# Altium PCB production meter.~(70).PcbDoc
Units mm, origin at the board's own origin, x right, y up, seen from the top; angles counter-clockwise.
Board outline 120 x 34 mm, 2 copper layers (Top Layer, Bottom Layer); 57 components, 53 nets, 214 pads, 22 vias.
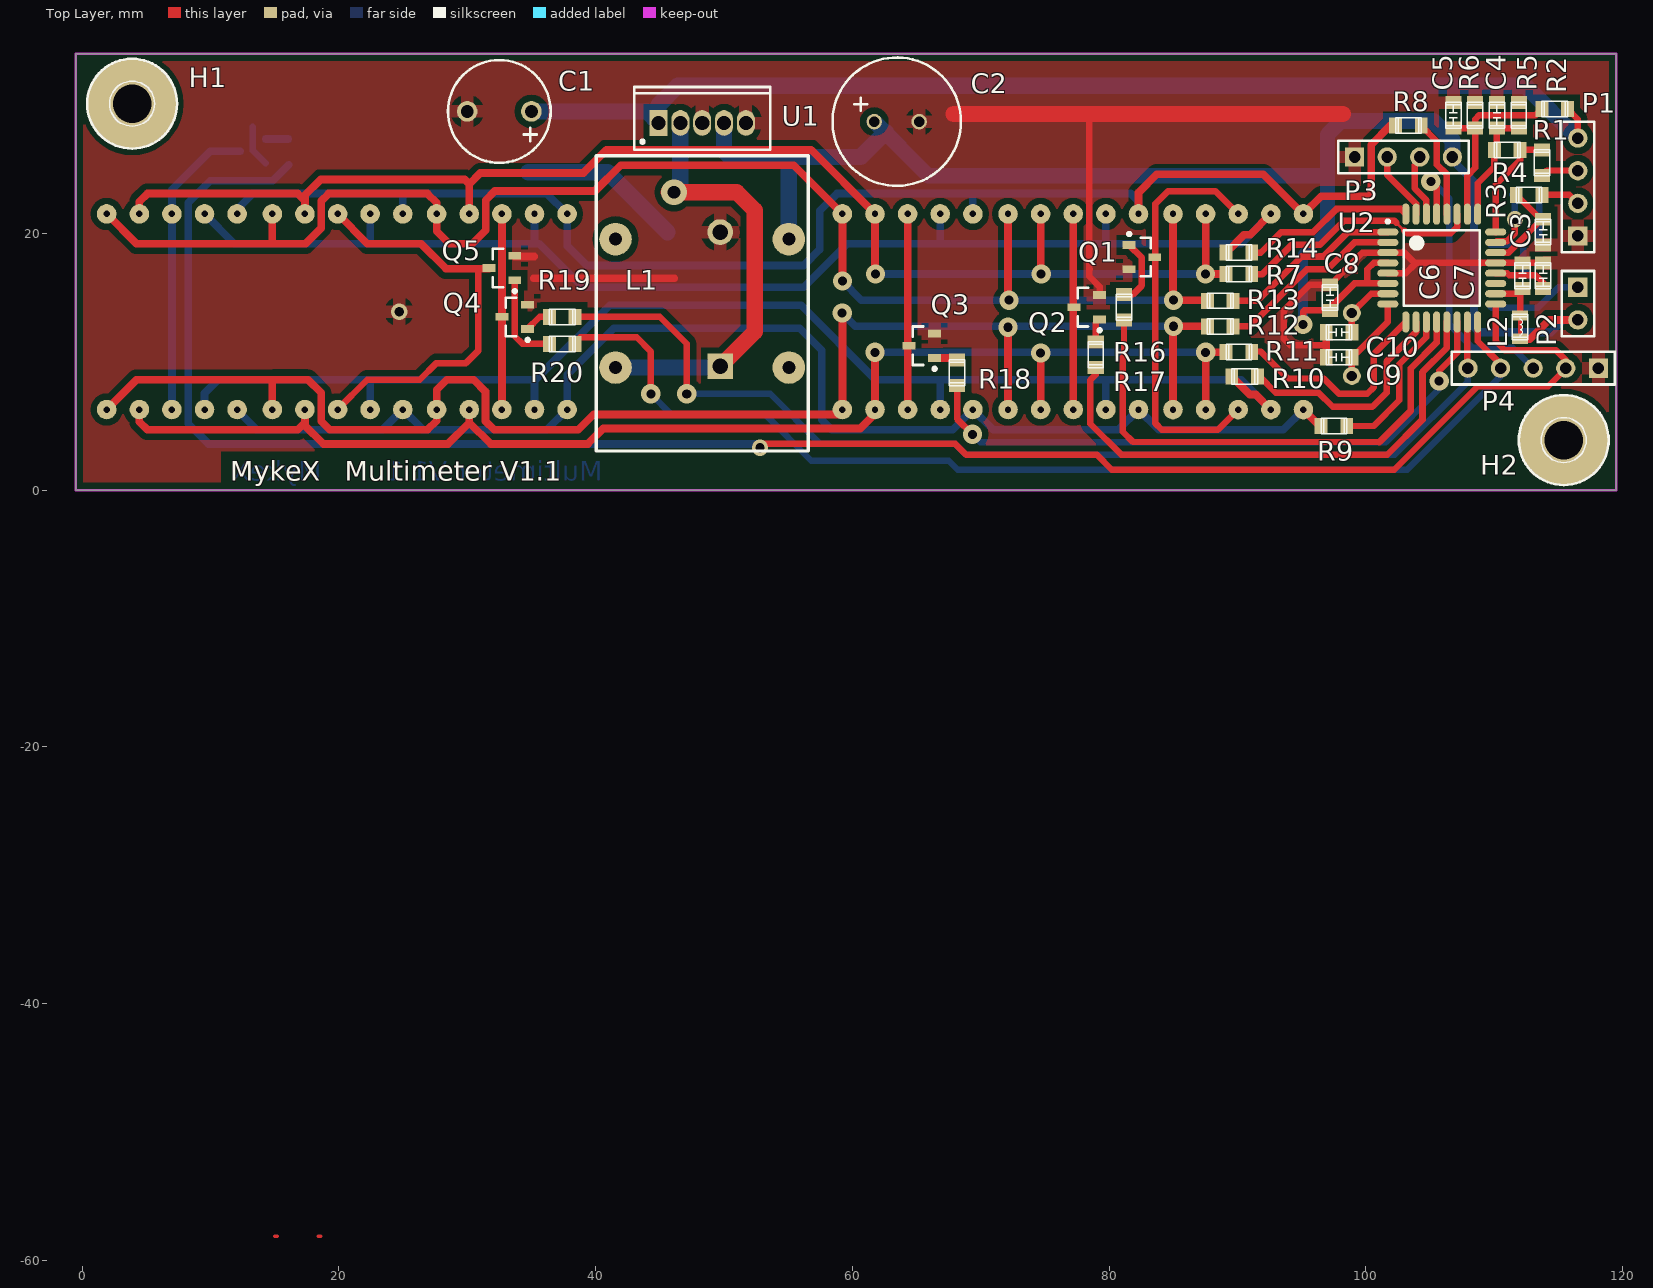
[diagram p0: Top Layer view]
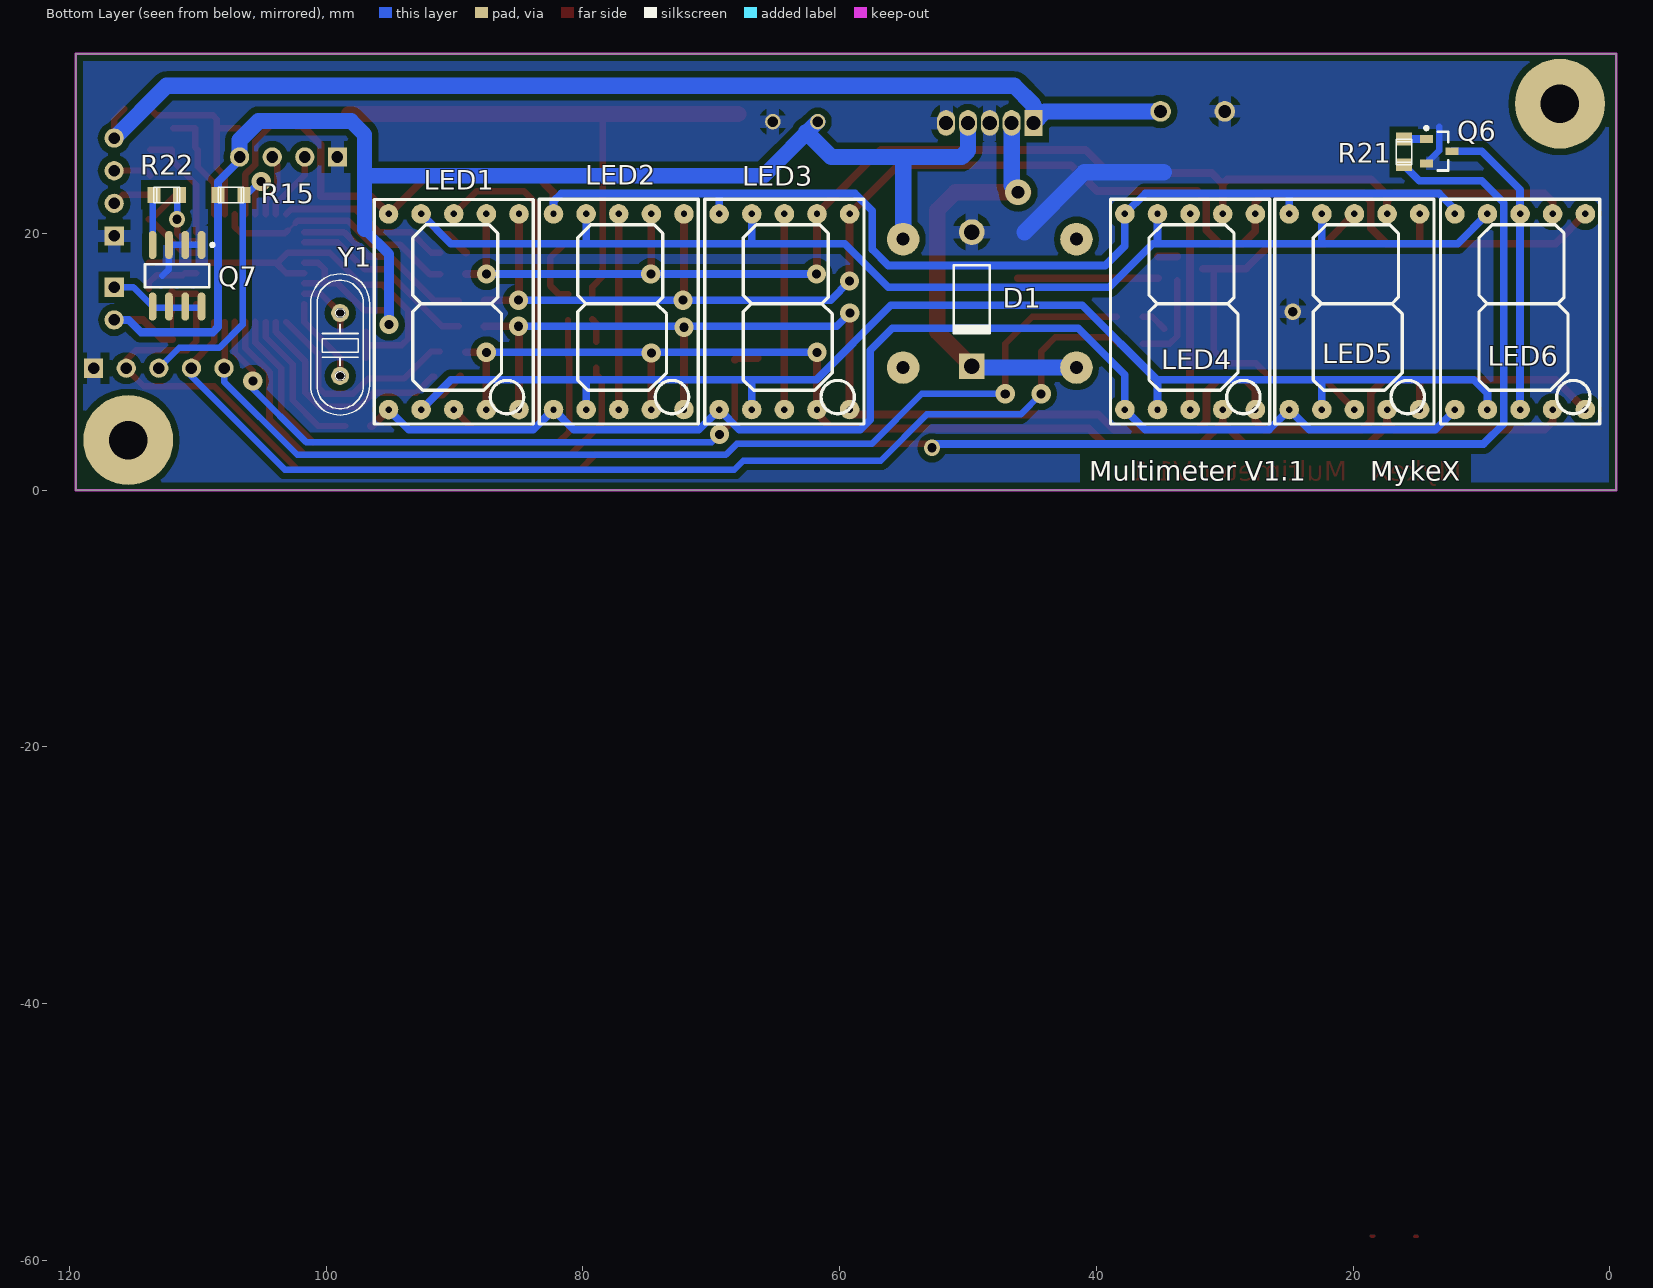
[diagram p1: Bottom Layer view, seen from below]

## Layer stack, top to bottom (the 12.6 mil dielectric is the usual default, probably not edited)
Top Layer: signal copper 0.0356
Dielectric: dielectric 0.32, FR-4, Dk 4.8
Bottom Layer: signal copper 0.0356

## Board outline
-0.5,0 -0.5,34 119.5,34 119.5,0

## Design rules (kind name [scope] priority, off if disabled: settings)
Clearance PolygonGND [InPolygon] p1: gap=0.5
Clearance [All] p2: gap=0.2
ComponentClearance [All] p1: gap=0.1 collisioncheckmode=3 verticalgap=0 showdistances=FALSE
HoleSize [All] p1: absolutevalues=TRUE maxlimit=5 minlimit=0.025 maxpercent=80.000 minpercent=20.000
MinimumSolderMaskSliver [All] p1: minsoldermaskwidth=0
PlaneClearance [All] p1: clearance=1
PlaneClearance PlaneClearance_1 [All] p2: clearance=0.8
PolygonConnect [All] p1: connectstyle=Relief reliefconductorwidth=1 reliefentries=4 polygonreliefangle="90 Angle"
RoomDefinition "production meter" [InComponentClass('production meter')] p1: confinementstyle=ConfineIn formatcopy=TRUE lockcomponents=FALSE outline -38,-58.1 12.8,-58.1 12.8,-32.7 -38,-32.7
RoutingVias [All] p1: holewidth=0.711 width=1.27 viastyle="Through Hole" minholewidth=0.711 minwidth=1.27 maxholewidth=2 maxwidth=2
SilkToSilkClearance [All] p1: silktosilkclearance=0
SilkscreenOverComponentPads [All] p1: minsilkscreentomaskgap=0
SolderMaskExpansion SolderMaskOverVia [(IsVia)] p1: expansion=-10
SolderMaskExpansion [All] p2: expansion=0.102
Width [All] p1: maxlimit=2 minlimit=0.2 preferedwidth=0.5
22 further rules are at their usual default settings.

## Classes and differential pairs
net class PD[7..0]: PD0 PD1 PD2 PD3 PD4 PD5 PD6 PD7
net class PB[5..0]: PB0 PB1 PB2 PB3 PB4 PB5

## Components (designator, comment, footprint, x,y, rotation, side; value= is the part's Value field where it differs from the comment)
C1 "100uFx50V" CEd8p5 35,29.5 r180 top
C2 "1000uFx3.6V" CEd10p3.5 61.7,28.7 r0 top
C3 "0.1uF" C0805\2P 113.8,21 r270 top
C4 "0.1uF" C0805\2P 110.2,28.3 r90 top
C5 "0.1uF" C0805\2P 106.8,28.3 r90 top
C6 "0.1uF" C0805\2P 112.2,17.6 r270 top
C7 "0.1uF" C0805\2P 113.8,17.6 r270 top
C8 "0.1uF" C0805\2P 97.2,14.1 r90 top
C9 "22pF" C0805\2P 97,10.352 r0 top
C10 "22pF" C0805\2P 97,12.3 r0 top
D1 "Diode 11DQ03" DIO10.46-5.3x2.8 49.7,14.87 r270 bottom
H1 "Hole_3mm" F3.5X7.5_Met_NH 3.9,30.1 r0 top
H2 "Hole_3mm" F3.5X7.5_Met_NH 115.4,3.9 r0 top
L1 "Inductor 330uH 1A" "Inductor footprint" 55.05,3.3 r90 top
L2 "47uH" LL0805\2P 112,13.6 r270 top
LED1 "SA52-11GWA" SA52-11GWA 96.249,5.148 r180 bottom
LED2 "SA52-11GWA" SA52-11GWA 83.4,5.15 r180 bottom
LED3 "SA52-11GWA" SA52-11GWA 70.5,5.15 r180 bottom
LED4 "SA52-11GWA" SA52-11GWA 38.9,5.15 r180 bottom
LED5 "SA52-11GWA" SA52-11GWA 26.1,5.15 r180 bottom
LED6 "SA52-11GWA" SA52-11GWA 13.2,5.15 r180 bottom
P1 "Header 4" HDR1X4 116.5,19.8 r90 top
P2 "Fan" HDR1X2 116.5,15.8 r270 top
P3 "UART" HDR1X4 99.11,25.95 r0 top
P4 "ISP Header" HDR1X5 118.1,9.5 r180 top
Q1 "BC847C" SOT23_L 82.55,18.15 r0 top
Q2 "BC847C" SOT23_L 78.25,14.25 r180 top
Q3 "BC847C" SOT23_L 65.4,11.25 r180 top
Q4 "BC847C" SOT23_L 33.7,13.5 r180 top
Q5 "BC847C" SOT23_L 32.7,17.3 r180 top
Q6 "BC847C" SOT23_L 13.3,26.4 r180 bottom
Q7 "IRF7811AV" SO-8_N 111.6,16.7 r270 bottom
R1 "260k" R0805\2P 113.7,26.4 r270 top
R2 "260k" R0805\2P 113.8,29.7 r0 top
R3 "1k" R0805\2P 111.8,23 r0 top
R4 "15k" R0805\2P 110.1,26.5 r0 top
R5 "30k" R0805\2P 111.9,30.1 r270 top
R6 "15k" R0805\2P 108.5,30.1 r270 top
R7 "180" R0805\2P 91,16.832 r180 top
R8 "180" R0805\2P 104.2,28.4 r180 top
R9 "180" R0805\2P 98.4,5 r180 top
R10 "180" R0805\2P 91.45,8.85 r180 top
R11 "180" R0805\2P 91,10.75 r180 top
R12 "180" R0805\2P 89.55,12.75 r180 top
R13 "180" R0805\2P 89.55,14.75 r180 top
R14 "180" R0805\2P 91,18.5 r180 top
R15 "10k" R0805\2P 108.3,23 r180 bottom
R16 "1k" R0805\2P 81.15,13.35 r90 top
R17 "1k" R0805\2P 78.95,9.65 r90 top
R18 "1k" R0805\2P 68.15,8.25 r90 top
R19 "1k" R0805\2P 38.3,13.5 r180 top
R20 "1k" R0805\2P 38.3,11.4 r180 top
R21 "1k" R0805\2P 16.05,25.45 r90 bottom
R22 "1k" R0805\2P 111.5,23 r0 bottom
U1 "LM2575T-5.0" T05A 48.3,28.6 r0 top
U2 "ATmega8-16AI" 32A_N 105.9,17.3 r0 top
Y1 "XTAL" XTAL_AXIAL_L11W4.6P4.9 98.9,13.8 r270 bottom

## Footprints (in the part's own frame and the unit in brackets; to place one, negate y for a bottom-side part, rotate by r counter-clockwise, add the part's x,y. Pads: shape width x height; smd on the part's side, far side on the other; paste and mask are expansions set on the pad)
32A_N [mm] "Thin QFP, 32-Leads, Body 7x7mm, Pitch 0.8mm, IPC Medium Density"
  oval 1.65x0.55 smd: 1(-4.2,2.8) 2(-4.2,2) 3(-4.2,1.2) 4(-4.2,0.4) 5(-4.2,-0.4) 6(-4.2,-1.2) 7(-4.2,-2) 8(-4.2,-2.8) 17(4.2,-2.8) 18(4.2,-2) 19(4.2,-1.2) 20(4.2,-0.4) 21(4.2,0.4) 22(4.2,1.2) 23(4.2,2) 24(4.2,2.8)
  oval 0.55x1.65 smd: 9(-2.8,-4.2) 10(-2,-4.2) 11(-1.2,-4.2) 12(-0.4,-4.2) 13(0.4,-4.2) 14(1.2,-4.2) 15(2,-4.2) 16(2.8,-4.2) 25(2.8,4.2) 26(2,4.2) 27(1.2,4.2) 28(0.4,4.2) 29(-0.4,4.2) 30(-1.2,4.2) 31(-2,4.2) 32(-2.8,4.2)
  silkscreen extent -4.32,-2.95 2.95,3.75, body extent -3.5,-3.5 3.5,3.5, height 1.2
C0805\2P [mm]
  rect 1x1.25 smd: 1(-0.1,0) 2(1.9,0)
  silkscreen extent -0.1,-0.6 1.9,0.6
CEd8p5 [mm] "Electrolytic capacitor, Diameter 8mm, Pitch 5mm"
  round 1.6 hole 1: 1(0,0) 2(5,0)
  silkscreen extent -1.5,-4 6.5,4
CEd10p3.5 [mm] "Electrolytic capacitor, Diameter 10mm, Pitch 3.5mm"
  round 1.2 hole 0.8: 1(0,0) 2(3.5,0)
  silkscreen extent -3.25,-5 6.75,5
DIO10.46-5.3x2.8 [mm] "Diode, Axial; Body 5.2 x 2.7 mm (LxDia. max), Lead Dia. 0.86 mm (max)"
  round 2 hole 1.2: 1(-5.23,0)
  rect 2x2 hole 1.2: 2(5.23,0)
  silkscreen extent -2.65,-1.41 2.75,1.4
F3.5X7.5_Met_NH [mm]
  round 7 hole 3: 0(0,0)
  silkscreen extent -3.5,-3.5 3.5,3.5
HDR1X2 [mm] "Connector; Header; 2 Position"
  rect 1.5x1.5 hole 0.9: 1(0,0)
  round 1.5 hole 0.9: 2(2.54,0)
  silkscreen extent -1.27,-1.27 3.81,1.27
HDR1X4 [mm] "Connector; Header; 4 Position"
  rect 1.5x1.5 hole 0.9: 1(0,0)
  round 1.5 hole 0.9: 2(2.54,0) 3(5.08,0) 4(7.62,0)
  silkscreen extent -1.27,-1.27 8.89,1.27
HDR1X5 [mm] "Connector; Header; 5 Position"
  rect 1.5x1.5 hole 0.9: 1(0,0)
  round 1.5 hole 0.9: 2(2.54,0) 3(5.08,0) 4(7.62,0) 5(10.16,0)
  silkscreen extent -1.27,-1.27 11.43,1.27
"Inductor footprint" [mm]
  round 2.54 hole 1: 0(6.25,0) 0(16.25,13.5) 1(6.25,13.5) 2(16.25,0)
  silkscreen extent -0.25,-1.5 22.75,15
LL0805\2P [mm]
  rect 0.8x1.25 smd: 1(0,0) 2(1.8,0)
  silkscreen extent -0.1,-0.6 1.9,0.6
R0805\2P [mm]
  rect 1x1.25 smd: 1(-0.1,0) 2(1.9,0)
  silkscreen extent -0.1,-0.6 1.9,0.6
SA52-11GWA [mm]
  round 1.524 hole 0.5: 1(1.12,1.13) 2(3.66,1.13) 3(6.2,1.13) 4(8.74,1.13) 5(11.28,1.13) 6(11.28,16.37) 7(8.74,16.37) 8(6.2,16.37) 9(3.66,16.37) 10(1.12,16.37)
  silkscreen extent 0,0 12.4,17.5
SO-8_N [mm] "SOIC, 8-Leads, Body 4.9x3.9mm, Pitch 1.27mm, IPC Medium Density"
  oval 2.2x0.6 smd: 1(-2.4,1.905) 2(-2.4,0.635) 3(-2.4,-0.635) 4(-2.4,-1.905) 5(2.4,-1.905) 6(2.4,-0.635) 7(2.4,0.635) 8(2.4,1.905)
  silkscreen extent -2.52,-2.5 0.9,2.88, body extent -1.95,-2.45 1.95,2.45, height 1.75
SOT23_L [mm] "SOT23, 3-Leads, Body 2.9x1.3mm, Pitch 0.95mm, Lead Span 2.3mm, IPC High Density"
  rect 1x0.6 smd: 1(-1,0.95) 2(-1,-0.95) 3(1,0)
  silkscreen extent -1.12,-1.5 0.7,1.92, body extent -0.7,-1.5 0.7,1.5, height 1.1
T05A [mm] "TO, Thru-Hole, Vertical, Heatsink Mounted; 5 In-Line Leads; Pitch 1.70 mm"
  rect 1.4x2 hole 1.1: 1(-3.4,0)
  oval 1.4x2 hole 1.1: 2(-1.7,0) 3(0,0) 4(1.7,0) 5(3.4,0)
  silkscreen extent -5.3,-2.1 5.3,2.8
XTAL_AXIAL_L11W4.6P4.9 [mm] "Quartz Crystal"
  round 1.4 hole 0.8: 1(0,0) 2(4.9,0)
  silkscreen extent -3.05,-2.3 7.95,2.3

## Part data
C1 C2: library part Cap_Elect, "Electrolytic capacitor"
C3 C4 C5 C6 C7 C8 C9 C10: library part Cap_Cer, "Capacitor ceramic"
D1: "Schottky Rectifier"
L1: library part "Inductor 330uH 1A_1"
L2: library part Inductor
P1: "Header, 4-Pin"
P2: library part "Header 2", "Header, 2-Pin"
P3: library part "Header 4", "Header, 4-Pin"
P4: library part "Header 5", "Header, 5-Pin"
Q1 Q2 Q3 Q4 Q5 Q6: "NPN General-purpose Transistor"
Q7: "HEXFET Power MOSFET"
R1 R2 R3 R4 R5 R6 R7 R8 R9 R10 R11 R12 R13 R14 R15 R16 R17 R18 R19 R20 R21 R22: library part Res, "Resistor"
U1: "SIMPLE SWITCHER 1A Step-Down Voltage Regulator"
U2: "8-Bit AVR Microcontroller with 8K Bytes of In-System Programmable Flash Memory"
Y1: "Quartz Crystal"

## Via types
v1: diameter 1.5, hole 0.711, Top Layer to Bottom Layer, 18 vias
v2: diameter 1.27, hole 0.711, Top Layer to Bottom Layer, 3 vias
v3: diameter 2, hole 1, Top Layer to Bottom Layer, 1 vias

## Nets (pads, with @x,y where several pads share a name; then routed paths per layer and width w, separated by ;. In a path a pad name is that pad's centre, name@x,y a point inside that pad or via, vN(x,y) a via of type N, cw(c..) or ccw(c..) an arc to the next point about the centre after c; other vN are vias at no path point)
GND: C1.2 C2.2 C3.2 C4.2 C5.2 C6.1 C7.1 C8.2 C9.1 C10.1 D1.1 P1.1 P3.1 P4.1 Q1.2 Q2.2 Q3.2 Q4.2 Q5.2 Q6.2 Q7.1 Q7.2 Q7.3 R5.1 R6.1 U1.3 U1.5 U2.3 U2.5 U2.21 | length 110.7
  Top Layer w0.5: 78.45,29.3 78.45,17.25 ; 78.5,17.2 78.45,17.25 ; Q2.2 79.25,15.85 78.45,16.65 78.45,17.25 ; 96.9,11.3 94.1,11.3 93.6,11.8 93.6,14 95.6,16 C8.2@97,16 ; C8.2@97.217,16 99.717,18.5 U2.3 103,18.5 103.8,17.7 U2.21 C6.1 C7.1 ; U2.5 103.1,16.9 103.85,17.65
  Top Layer w0.6: Q5.2@33.7,18.2 35.2,18.2 ; 35.2,16.5 46.1,16.5 ; C9.1 96.9,11.3 C10.1
  Top Layer w1.27: 67.9,29.3 78.45,29.3 98.2,29.3
  Bottom Layer w0.5: 13.3,28.3 13.3,26.45 Q6.2 ; Q7.1 Q7.2 Q7.3 112.235,17.215 112.75,16.7
  Bottom Layer w1.27: 34.75,24.75 40.95,24.75 45.6,20.1
  other v2: 24.7,13.9
NetC1_1: C1.1 P1.4 R2.2 U1.1 | length 88.2
  Top Layer w0.5: R2.2 116.5,28.9 P1.4 P1.4@116.48,27.42
  Bottom Layer w1.27: C1.1 44,29.5 U1.1 44.9,30 46.4,31.5 112.42,31.5 P1.4
NetC3_1: C3.1 R3.1 U2.22 | length 7.6
  Top Layer w0.5: U2.22 111.1,18.5 C3.1@113.7,21.1 ; R3.1 113.6,21.1 C3.1@113.7,21.1 ; C3.1 C3.1@113.7,21.1
NetC4_1: C4.1 R4.1 R5.2 U2.25 | length 9
  Top Layer w0.5: U2.25 108.7,23.9 110,25.2 R4.1 110.2,26.7 C4.1 R5.2
NetC5_1: C5.1 R2.1 R6.2 U2.26 | length 14.9
  Top Layer w0.5: C5.1 R6.2 ; U2.26 107.9,24.5 108.5,25.1 R6.2 ; R2.1 113.2,29.2 108.8,29.2 108.5,28.9 R6.2
NetC7_2: C7.2 U2.20 | length 4.5
  Top Layer w0.5: U2.20 111,16.9 111.15,16.75 113.2,16.75 113.8,16.15 C7.2
NetC9_2: C9.2 U2.8 Y1.2 | length 6.8
  Top Layer w0.5: Y1.2 98.9,10.3 101.7,13.1 U2.8
NetC10_2: C10.2 U2.7 Y1.1 | length 4.9
  Top Layer w0.5: C10.2 Y1.1 100.4,15.3 U2.7
NetD1_2: D1.2 L1.1 U1.2 | length 34.3
  Top Layer w1.27: v3@45.7,23.2 51,23.2 52.4,21.8 52.4,12.34 D1.2
  Bottom Layer w1.27: L1.1 D1.2@49.7,9.55 ; v3(46.1,23.2) 46.6,23.7 U1.2
NetLED1_3: LED1.3 LED1.8 Q1.3 | length 32.1
  Top Layer w0.508: LED1.8 88.267,23.3 84.6,23.3 83.6,22.3 83.6,5.2 84.1,4.7 88.471,4.7 LED1.3 LED1.3@90.1,6.227
NetLED2_3: LED2.3 LED2.8 Q2.3 | length 15.2
  Top Layer w0.6: LED2.3 LED2.8
NetLED3_3: LED3.3 LED3.8 Q3.3 | length 15.2
  Top Layer w0.6: LED3.3 LED3.8
NetLED4_3: LED4.3 LED4.8 Q4.3 | length 15.2
  Top Layer w0.6: LED4.3 LED4.8
NetLED5_3: LED5.3 LED5.8 Q5.3 | length 33.6
  Top Layer w0.508: LED5.3 22.22,8.6 26.3,8.6 27.6,9.9 29.9,9.9 30.87,10.87 30.87,17.25 Q5.3@31.7,17.25
  Top Layer w0.6: LED5.8 22.22,19.2 26.4,19.2 28.35,17.25 Q5.3@31.7,17.25
NetLED6_3: LED6.3 LED6.8 Q6.3 | length 23.7
  Bottom Layer w0.6: LED6.3 LED6.8 7,23.4 10,26.4 Q6.3
NetP1_2: P1.2 R3.2 | length 3.1
  Top Layer w0.5: R3.2 115.84,23 P1.2
NetP1_3: P1.3 R1.2 | length 3
  Top Layer w0.5: R1.2 114.1,24.9 116.48,24.9 P1.3
NetP2_1: P2.1 Q7.5 Q7.6 Q7.7 Q7.8 | length 7.7
  Bottom Layer w0.5: Q7.8 109.795,14.2 112.235,14.2 Q7.5@113.4,14.2 ; Q7.5@113.5,14.3 Q7.5@113.4,14.2 ; P2.1 115,15.8 Q7.5@113.4,14.2
NetP3_2: P3.2 U2.31 | length 5.1
  Top Layer w0.5: P3.2@101.64,25.7 101.64,24.56 103.9,22.3 U2.31
NetP3_3: P3.3 U2.30 | length 4.7
  Top Layer w0.5: P3.3@104.18,25.7 103.8,25.32 103.8,23.5 104.7,22.6 U2.30
NetP4_3: P4.3 R15.2 U2.29 | length 22.5
  Top Layer w0.5: v1@105,24.1 105.5,23.6 U2.29
  Bottom Layer w0.5: v1@105.1,24.1 106.5,22.7 106.5,12.9 108.3,11.1 111.42,11.1 P4.3
  other v1: 105.05,24.05
NetQ1_1: Q1.1 R16.2 | length 5.3
  Top Layer w0.508: R16.2 81.85,15.25 82.55,15.95 82.55,18.1 Q1.1
NetQ2_1: Q2.1 R17.2 | length 1.9
  Top Layer w0.508: R17.2 78.95,13 Q2.1
NetQ3_1: Q3.1 R18.2 | length 1.8
  Top Layer w0.6: Q3.1 68,10.3 R18.2
NetQ4_1: Q4.1 R19.2 | length 2.1
  Top Layer w0.5: Q4.1 35.65,13.5 R19.2
NetQ5_1: Q5.1 R20.2 | length 7.3
  Top Layer w0.5: Q5.1 33.7,12 34.3,11.4 R20.2
NetQ6_1: Q6.1 R21.2 | length 1.7
  Bottom Layer w0.6: Q6.1 R21.2
NetQ7_4: Q7.4 R22.2 | length 4
  Bottom Layer w0.5: Q7.4 R22.2@113.505,23.1
NetR1_1: R1.1 R4.2 U2.24 | length 8.9
  Top Layer w0.5: U2.24 110.1,23.8 112,25.7 R4.2 R1.1
NetR7_1: R7.1 U2.27 | length 19.2
  Top Layer w0.2: 102.5,20.7 102.975,20.225
  Top Layer w0.5: 102.975,20.225 103.2,20 106.6,20 107.1,20.5 U2.27
  Top Layer w0.508: R7.1@91.1,16.8 91.9,16.8 94.2,19.1 96.4,19.1 98.3,21 102.2,21 102.371,20.829
NetR8_1: R8.1 U2.28 | length 7.7
  Top Layer w0.508: R8.1 105.516,27.184 105.516,25.364 106.3,24.58 U2.28
NetR9_1: R9.1 U2.11 | length 11.9
  Top Layer w0.5: R9.1 100.6,5 102.6,7 102.6,9.8 104.7,11.9 U2.11
NetR10_1: R10.1 U2.10 | length 17.9
  Top Layer w0.5: R10.1 91.731,8.85 92.981,7.6 96.3,7.6 97.4,6.5 100.5,6.5 101.6,7.6 101.6,10.025 103.9,12.325 U2.10
NetR11_1: R11.1 U2.9 | length 17.2
  Top Layer w0.5: R11.1@91.15,10.8 91.8,10.8 92.15,10.45 93.9,8.7 96.7,8.7 97.9,7.5 100.1,7.5 100.6,8 100.6,10.6 U2.9
NetR12_1: R12.1 U2.2 | length 14.8
  Top Layer w0.508: R12.1 90.95,12.75 95.4,17.2 97,17.2 99.1,19.3 U2.2
NetR13_1: R13.1 U2.1 | length 14.3
  Top Layer w0.508: R13.1 91.55,14.75 95,18.2 96.7,18.2 98.6,20.1 U2.1
NetR14_1: R14.1 U2.32 | length 13.6
  Top Layer w0.508: R14.1 91.8,18.5 93.4,20.1 95.9,20.1 97.7,21.9 102.7,21.9 U2.32
NetR22_1: R22.1 U2.23 | length 4.9
  Top Layer w0.5: U2.23 110.175,19.375 110.95,19.375 111.6,20.025 v2(111.6,21.1)
  Bottom Layer w0.5: R22.1 111.6,22.8 v2(111.6,21.1)
PB0: R16.1 U2.12 | length 40.3
  Top Layer w0.5: R16.1 81.15,10.45 81.05,10.35 81.05,4.55 81.85,3.75 101.05,3.75
  Top Layer w0.508: 101.05,3.75 103.5,6.2 103.5,9.5 105.5,11.5 U2.12
PB1: R17.1 U2.13 | length 41
  Top Layer w0.508: 78.55,8.6 78.524,8.574 ; R17.1 78.95,9 78.524,8.574 ; U2.13 106.3,11.1 104.4,9.2 104.4,5.5 101.65,2.75 80.95,2.75 78.524,5.176 78.524,8.574
PB2: R18.1 U2.14 | length 48.5
  Top Layer w0.508: R18.1@68.15,8.25 68.15,5.55 v1(69.35,4.35) ; v1(105.7,8.5) 105.7,9.3 107.1,10.7 U2.14
  Bottom Layer w0.508: v1(69.35,4.35) 69.95,3.75 101.55,3.75 105.7,7.9 v1(105.7,8.5)
PB3: P4.5 R19.1 U2.15 | length 83.3
  Top Layer w0.5: R19.1 45,13.5 47.1,11.4 v1(47.1,7.5) ; P4.5@107.9,9.5 U2.15
  Bottom Layer w0.5: v1(47.1,7.5) 53.6,7.5 57.5,3.6 68,3.6 68.85,2.75 102.25,2.75 107.94,8.44 P4.5
PB4: P4.4 R20.1 U2.16 | length 87
  Top Layer w0.5: R20.1@38.3,11.4 38.8,11.9 43.2,11.9 44.3,10.8 v1(44.3,7.5) ; U2.16 108.7,11.6 110.48,9.82 P4.4@110.48,9.02
  Bottom Layer w0.5: v1(44.3,7.5) 45.9,5.9 53.2,5.9 56.8,2.3 67.5,2.3 68.2,1.6 103.2,1.6 110.48,8.88 P4.4
PB5: P4.2 R21.1 U2.17 | length 148
  Top Layer w0.5: v2@52.9,3.5 53,3.6 68,3.6 68.85,2.75 79.05,2.75 80.2,1.6 102.2,1.6 108.7,8.1 114.2,8.1 115.56,9.46 115.56,10.14 114.8,10.9 110.8,10.9 110.1,11.6 U2.17
  Bottom Layer w0.6: R21.1@16.1,25.35 14.85,24.1 10,24.1 8.278,22.378 8.278,5.172 9.85,3.6 52.5,3.6 v2(52.8,3.3)
PD0: LED1.10 LED2.10 LED3.10 LED4.10 LED5.10 LED6.10 R8.2 | length 112
  Top Layer w0.6: LED2.10 82.28,23.18 83.7,24.6 92,24.6 95.082,21.518 LED1.10 96.511,22.9 100.4,22.9 100.4,26.9 101.9,28.4 R8.2
  Bottom Layer w0.6: LED6.10 12.08,21.88 13.3,23.1 25,23.1 ; LED5.10 24.98,23.08 25,23.1 ; LED3.10 69.38,23.08 ; LED2.10 82.28,22.5 81.68,23.1 58.8,23.1 57.45,21.75 57.45,18.75 56.2,17.5 39.3,17.5 37.78,19.02 LED4.10 36.2,23.1 25,23.1
PD1: LED1.9 LED2.9 LED3.9 LED4.9 LED5.9 LED6.9 R14.2 | length 101.6
  Top Layer w0.6: R14.2 90.5,19.9 90.971,19.9 LED1.9
  Bottom Layer w0.6: LED6.9 11.86,19.2 35.6,19.2 39,15.8 56.2,15.8 59.6,19.2 90.271,19.2 LED1.9 ; 22.44,19.24 LED5.9 ; 35.24,19.24 LED4.9 ; 66.84,19.24 LED3.9 ; 79.74,19.24 LED2.9
PD2: LED1.7 LED2.7 LED3.7 LED4.7 LED5.7 LED6.7 R7.2 | length 107.6
  Top Layer w0.6: LED6.7 4.46,22.46 5.1,23.1 16.8,23.1 17.36,22.54 ; LED5.7 17.36,22.54 ; LED4.7 30.16,23.84 ; v1@61.76,16.892 LED3.7 56.78,26.5 40.85,26.5 39.05,24.7 31.02,24.7 30.16,23.84 ; v1@74.66,16.872 LED2.7 ; LED1.7 87.509,16.832 R7.2 ; 17.36,22.54 17.36,22.96 18.6,24.2 29.8,24.2 30.16,23.84
  Bottom Layer w0.6: v1(61.8,16.832) v1(74.7,16.832) v1(87.5,16.832)
PD3: LED1.6 LED2.6 LED3.6 LED4.6 LED5.6 LED6.6 R13.2 | length 119.6
  Top Layer w0.6: LED6.6 4.24,19.2 14.82,19.2 ; LED5.6 14.82,19.2 ; v1@59.2,16.3 59.22,16.32 LED3.6 55.44,25.3 41.95,25.3 39.95,23.3 32.15,23.3 31.438,22.588 31.438,20.238 30.4,19.2 28.6,19.2 27.62,20.18 LED4.6 27.62,22.38 26.9,23.1 19.2,23.1 18.622,22.522 18.622,20.422 17.4,19.2 14.82,19.2 ; v1@72.1,14.8 72.12,14.82 LED2.6 ; LED1.6 84.969,14.831 v1(85,14.8) 87.6,14.8 R13.2
  Bottom Layer w0.6: v1@59.2,16.3 60.7,14.8 v1(72.2,14.8) v1(85,14.8)
  other v1: 59.22,16.3
PD4: LED1.5 LED2.5 LED3.5 LED4.5 LED5.5 LED6.5 R12.2 | length 119.7
  Top Layer w0.6: LED6.5 4.24,8.6 14.82,8.6 ; LED5.5 14.82,8.6 ; LED3.5@59.22,5.9 39.85,5.9 38.65,4.7 32.1,4.7 31.422,5.378 31.422,7.678 30.5,8.6 28.4,8.6 27.62,7.82 LED4.5 27.62,5.42 26.9,4.7 19.3,4.7 18.622,5.378 18.622,7.578 17.6,8.6 14.82,8.6 ; LED3.5 v1@59.22,14.06 ; LED2.5 v1(72.12,12.688) ; LED1.5 84.969,12.769 v1@85,12.8 ; v1@85.032,12.8 v1(85,12.768) 87.632,12.768 R12.2
  Bottom Layer w0.6: v1(59.2,13.8) 60.232,12.768 v1@72.2,12.768 ; v1(72.12,12.688) v1@72.2,12.768 ; v1(85,12.768) v1@72.2,12.768
PD5: LED1.4 LED2.4 LED3.4 LED4.4 LED5.4 LED6.4 R11.2 | length 104.9
  Top Layer w0.6: LED6.4 4.46,5.34 5.1,4.7 16.8,4.7 17.36,5.26 ; LED5.4 17.36,5.26 ; LED4.4 30.16,5.26 ; v1@61.76,10.736 LED3.4 61.76,5.96 60.6,4.8 40.6,4.8 39.4,3.6 31.82,3.6 30.16,5.26 ; LED2.4 v1(74.66,10.676) ; LED1.4 v1@87.509,10.709 ; v1@87.536,10.736 R11.2@89.1,10.736 ; 17.36,5.26 17.36,5.04 18.8,3.6 28.5,3.6 30.16,5.26
  Bottom Layer w0.6: v1@61.764,10.736 v1(87.509,10.736)
  other v1: 61.75,10.736
PD6: LED1.2 LED2.2 LED3.2 LED4.2 LED5.2 LED6.2 R10.2 | length 103.8
  Top Layer w0.6: R10.2 90.95,7.45 91.417,7.45 LED1.2
  Bottom Layer w0.6: LED6.2 9.54,7.54 10.6,8.6 22.5,8.6 ; LED5.2 22.44,8.54 22.5,8.6 ; 35.2,8.6 22.5,8.6 ; LED4.2 35.24,8.54 41.1,14.4 56,14.4 61.8,8.6 66.8,8.6 ; LED3.2 66.84,8.56 66.8,8.6 ; LED2.2 79.74,8.54 ; LED1.2 90.267,8.6 66.8,8.6
PD7: LED1.1 LED2.1 LED3.1 LED4.1 LED5.1 LED6.1 R9.2 | length 101.5
  Top Layer w0.6: LED1.1 96.407,5 R9.2
  Bottom Layer w0.6: LED6.1 12.08,6.22 13.6,4.7 23.4,4.7 LED5.1 26.56,4.7 36.2,4.7 LED4.1 37.78,8.98 41.4,12.6 55.9,12.6 57.6,10.9 57.6,5.5 58.4,4.7 67.8,4.7 LED3.1 70.96,4.7 80.7,4.7 LED2.1 83.86,4.7 93.551,4.7 LED1.1
VCC: C2.1 C6.2 C8.1 L1.2 L2.1 L2.2 P2.2 P3.4 R15.1 U1.4 U2.4 U2.6 U2.18 | length 131.5
  Top Layer w0.3: L2.2@112,11.9 L2.1@112,13.7
  Top Layer w0.5: v1(95.1,12.9) 95.1,13.9 95.2,14 97,14 99.1,16.1 U2.6 ; 100.1,16.1 100.1,17.2 100.6,17.7 U2.4 ; U2.18 111.8,15.3 112,15.5 112,13.9 L2.1@112.2,13.7
  Top Layer w0.6: L2.2@112,11.76 112.76,11.76 114.26,13.26 P2.2
  Bottom Layer w0.635: P3.4@106.72,25.7 108.4,24.02 108.4,12.7 108.8,12.3 114.4,12.3 115.36,13.26 P2.2
  Bottom Layer w0.8: v1(95.1,12.9) 95.1,18.4 97,20.3
  Bottom Layer w1.2: C2.1 65.9,24.5 97,24.5 ; 97,20.3 97,27.7 98.05,28.75
  Bottom Layer w1.27: U1.4 50,26.45 50.5,25.95 55.05,25.95 ; L1.2 55.05,25.95 ; 62.6,27.9 60.65,25.95 55.05,25.95 ; 98.05,28.75 105.25,28.75 106.73,27.27 P3.4
pads on no net: H1.0 H2.0 L1.0 U2.19
copper on no net: | length 0.4
  Top Layer w0.254: 15,-58.1 15.2,-58.1 ; 18.4,-58.1 18.6,-58.1

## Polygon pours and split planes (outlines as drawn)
GND on Top Layer "Bottom Layer-No Net" (solid, remove dead copper, pour order 1000): 0,0 0,36 119.5,36 119.5,0 0,0
GND on Bottom Layer "Bottom Layer-No Net" (solid, remove dead copper, pour order 1001): 0,0 0,36 119.5,36 119.5,0 0,0

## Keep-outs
Keep-Out Layer:
  the board outline again, w0.2

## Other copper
Top Layer:
  text "MykeX" at 11.54,0.75 h1.52
  text "Multimeter V1.1" at 20.45,0.75 h1.52
Bottom Layer:
  text "MykeX" at 18.65,0.75 h1.52
  text "Multimeter V1.1" at 40.55,0.75 h1.52

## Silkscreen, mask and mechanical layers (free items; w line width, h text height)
Top Overlay:
  text "MykeX" at 11.54,0.75 h1.52
  text "Multimeter V1.1" at 20.45,0.75 h1.52
Bottom Overlay:
  text "MykeX" at 18.65,0.75 h1.52
  text "Multimeter V1.1" at 40.55,0.75 h1.52

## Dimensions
119.5,34 to 119.5,0 on Mechanical 13
119.5,34 to -0.5,34 on Mechanical 13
